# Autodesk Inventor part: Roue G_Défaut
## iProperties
Shininess: 64.0
Length Units: 11269
Angle Units: 11279
Time Units: 11290
Mass Units: 11283
Length Display Precision: 3
Angle Display Precision: 2
Compacted: True
Part Number: Roue G_Défaut
Document SubType Name: Modeling
Created: 2006-01
Material: Par défaut
Designer: Fricot
Density: 0.0
Volumn: 0.0
Area: 0.0
PropertySet Name: Model Information
Control State: 0
Master: False
Checked Out: False
Author: Fricot
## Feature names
1. Base1
